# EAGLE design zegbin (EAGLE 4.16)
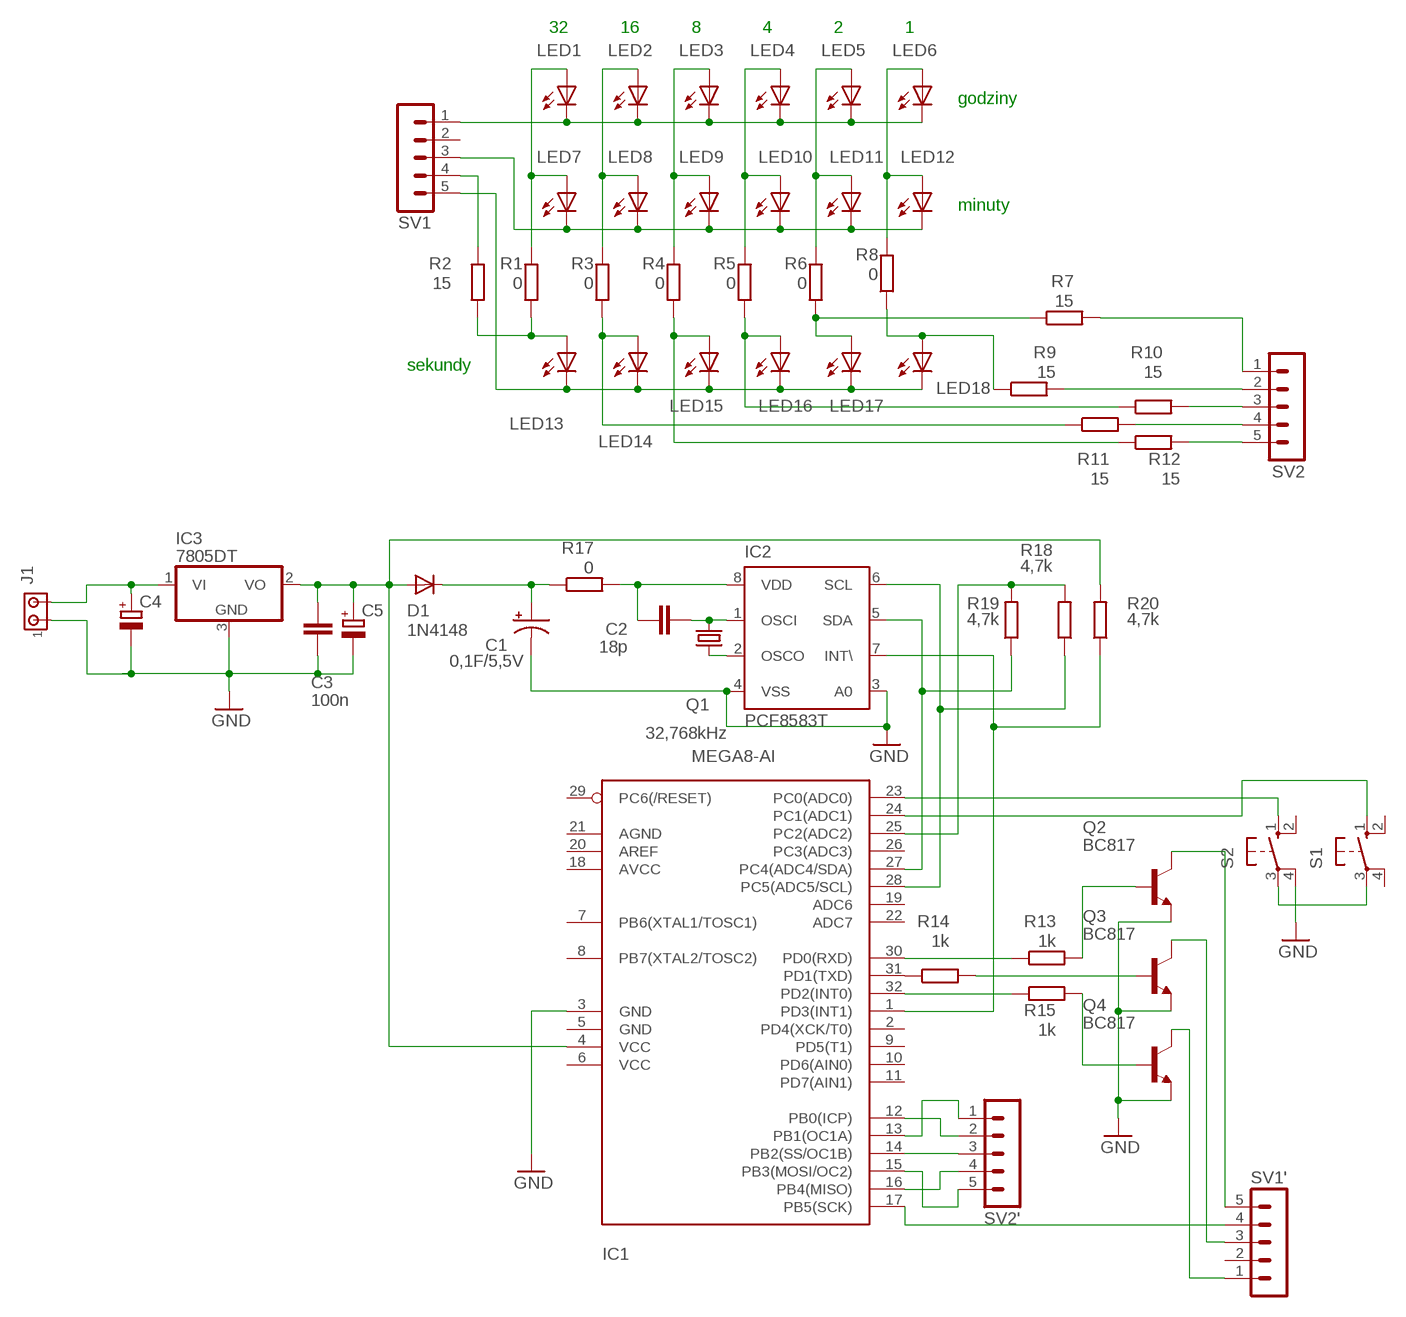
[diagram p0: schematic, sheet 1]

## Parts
C1  0,1F/5,5V  CPOL-USE5-13  [E5-13]
C2  18p  C-EUC1206  [C1206]
C3  100n  C-EUC1206  [C1206]
C4  CPOL-EU085CS-1AR  [085CS_1AR]
C5  CPOL-EU085CS-1AR  [085CS_1AR]
D1  1N4148  PMLL4150  [SOD80C]
IC1  MEGA8-AI  [TQFP32-08]
IC2  PCF8583T  [SO8-7_5]
IC3  7805DT  [TO252]
J1  MTA02-100  [10X02MTA]
LED1  LED5MM  [LED5MM]
LED2  LED5MM  [LED5MM]
LED3  LED5MM  [LED5MM]
LED4  LED5MM  [LED5MM]
LED5  LED5MM  [LED5MM]
LED6  LED5MM  [LED5MM]
LED7  LED5MM  [LED5MM]
LED8  LED5MM  [LED5MM]
LED9  LED5MM  [LED5MM]
LED10  LED5MM  [LED5MM]
LED11  LED5MM  [LED5MM]
LED12  LED5MM  [LED5MM]
LED13  LED5MM  [LED5MM]
LED14  LED5MM  [LED5MM]
LED15  LED5MM  [LED5MM]
LED16  LED5MM  [LED5MM]
LED17  LED5MM  [LED5MM]
LED18  LED5MM  [LED5MM]
Q1  32,768kHz  CRYSTALTC26H  [TC26H]
Q2  BC817  BC817-25SMD  [SOT23-BEC]
Q3  BC817  BC817-25SMD  [SOT23-BEC]
Q4  BC817  BC817-25SMD  [SOT23-BEC]
R1  0  R-EU_M1206  [M1206]
R2  15  R-EU_M1206  [M1206]
R3  0  R-EU_M1206  [M1206]
R4  0  R-EU_M1206  [M1206]
R5  0  R-EU_M1206  [M1206]
R6  0  R-EU_M1206  [M1206]
R7  15  R-EU_M1206  [M1206]
R8  0  R-EU_M1206  [M1206]
R9  15  R-EU_M1206  [M1206]
R10  15  R-EU_M1206  [M1206]
R11  15  R-EU_M1206  [M1206]
R12  15  R-EU_M1206  [M1206]
R13  1k  R-EU_M1206  [M1206]
R14  1k  R-EU_M1206  [M1206]
R15  1k  R-EU_M1206  [M1206]
R17  0  R-EU_M1206  [M1206]
R18  4,7k  R-EU_M1206  [M1206]
R19  4,7k  R-EU_M1206  [M1206]
R20  4,7k  R-EU_M1206  [M1206]
S1  10-XX  [B3F-10XX]
S2  10-XX  [B3F-10XX]
SV1  MA05-1  [MA05-1]
SV1'  MA05-1  [MA05-1]
SV2  MA05-1  [MA05-1]
SV2'  MA05-1  [MA05-1]

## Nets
GND: C1.- C3.1 C4.- C5.- IC1.3(GND) IC2.3(A0) IC2.4(VSS) IC3.3(GND) J1.1 Q2.E Q3.E Q4.E S2.4(P1)
N$1: LED1.K(C) LED2.K(C) LED3.K(C) LED4.K(C) LED5.K(C) LED6.K(C) SV1.1
N$2: LED7.K(C) LED8.K(C) LED9.K(C) LED10.K(C) LED11.K(C) LED12.K(C) SV1.3
N$3: LED13.K(C) LED14.K(C) LED15.K(C) LED16.K(C) LED17.K(C) LED18.K(C) SV1.5
N$4: LED1.A LED7.A R1.2
N$5: LED2.A LED8.A R3.2
N$6: LED3.A LED9.A R4.2
N$7: LED4.A LED10.A R5.2
N$8: LED5.A LED11.A R6.2
N$9: LED6.A LED12.A R8.2
N$10: LED13.A R1.1 R2.1
N$11: R2.2 SV1.4
N$12: LED14.A R3.1 R11.1
N$13: LED15.A R4.1 R12.1
N$14: LED16.A R5.1 R10.1
N$15: LED17.A R6.1 R7.1
N$16: R7.2 SV2.1
N$17: LED18.A R8.1 R9.1
N$18: R9.2 SV2.2
N$19: R10.2 SV2.3
N$20: R11.2 SV2.4
N$21: R12.2 SV2.5
N$22: C2.2 IC2.1(OSCI) Q1.2
N$23: IC2.2(OSCO) Q1.1
N$24: IC1.12(PB0(ICP)) SV2'.2
N$25: IC1.13(PB1(OC1A)) SV2'.1
N$26: IC1.14(PB2(SS/OC1B)) SV2'.3
N$27: IC1.16(PB4(MISO)) SV2'.4
N$28: IC1.15(PB3(MOSI/OC2)) SV2'.5
N$29: IC1.17(PB5(SCK)) SV1'.4
N$30: IC1.30(PD0(RXD)) R13.1
N$31: IC1.31(PD1(TXD)) R14.1
N$32: IC1.32(PD2(INT0)) R15.1
N$33: Q2.B R13.2
N$34: Q3.B R14.2
N$35: Q4.B R15.2
N$36: IC1.23(PC0(ADC0)) S2.1(S)
N$37: Q2.C SV1'.5
N$38: Q3.C SV1'.3
N$39: Q4.C SV1'.1
N$40: IC1.24(PC1(ADC1)) S1.1(S)
N$41: IC1.27(PC4(ADC4/SDA)) IC2.5(SDA) R19.1
N$43: IC1.28(PC5(ADC5/SCL)) IC2.6(SCL) R18.1
N$44: IC1.1(PD3(INT1)) IC2.7(INT\) R20.1
N$45: S1.3(P) S2.3(P)
N$46: C1.+ D1.C R17.1
N$48: C2.1 IC2.8(VDD) R17.2
N$49: C3.2 C5.+ D1.A IC1.4(VCC) IC3.2(VO) R20.2
N$50: C4.+ IC3.1(VI) J1.2
N$51: IC1.25(PC2(ADC2)) R18.2 R19.2
Unconnected: IC1.2(PD4(XCK/T0)) IC1.5(GND) IC1.6(VCC) IC1.7(PB6(XTAL1/TOSC1)) IC1.8(PB7(XTAL2/TOSC2)) IC1.9(PD5(T1)) IC1.10(PD6(AIN0)) IC1.11(PD7(AIN1)) IC1.18(AVCC) IC1.19(ADC6) IC1.20(AREF) IC1.21(AGND) IC1.22(ADC7) IC1.26(PC3(ADC3)) IC1.29(PC6(/RESET)) S1.2(S1) S1.4(P1) S2.2(S1) SV1'.2 SV1.2

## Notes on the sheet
- 32 | 16 | 8 | 4 | 2 | 1
- godziny
- minuty
- sekundy

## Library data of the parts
C1 = rcl:CPOL-US: POLARIZED CAPACITOR, American symbol
C2 C3 = rcl:C-EU: CAPACITOR, European symbol
C4 C5 = rcl:CPOL-EU: POLARIZED CAPACITOR, European symbol
D1 = diode:PMLL4150: DIODE
IC1 = avr-1:MEGA8: MICROCONTROLLER 8 Kbytes FLASH 1 kbytes SRAM 512 bytes EEPROM USART 6-channel 10 bit ADC 2-channel 8 bit ADC
IC2 = ds1307_pcf8583:PCF8583: I2C-Bus CLOCK/CALENDAR
IC3 = linear:78*: Positive VOLTAGE REGULATOR Source: http://cache.national.com/ds/LM/LM78L05.pdf http://www.fairchildsemi.com/ds/LM/LM7805.pdf
J1 = con-amp:MTA02-100: AMP connector
LED1-LED18 = led:LED: LED
Q1 = crystal:CRYSTAL: CRYSTAL
Q2-Q4 = transistor-npn:BC817*: NPN Transistor
R1-R15 R17-R20 = rcl:R-EU_: RESISTOR, European symbol
S1 S2 = switch-omron:10-XX: OMRON SWITCH
SV1 SV1' SV2 SV2' = con-lstb:MA05-1: PIN HEADER

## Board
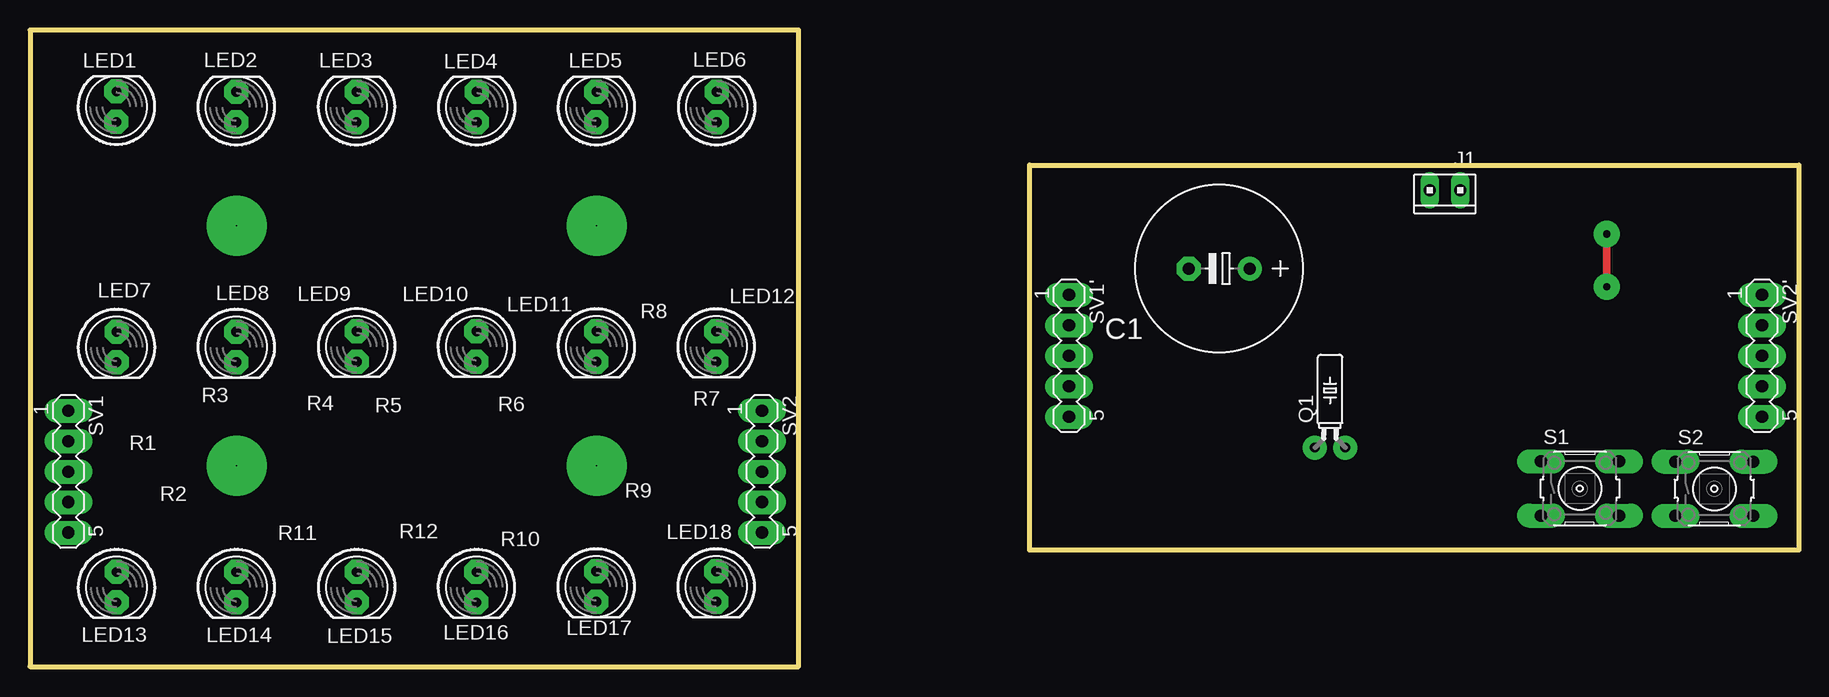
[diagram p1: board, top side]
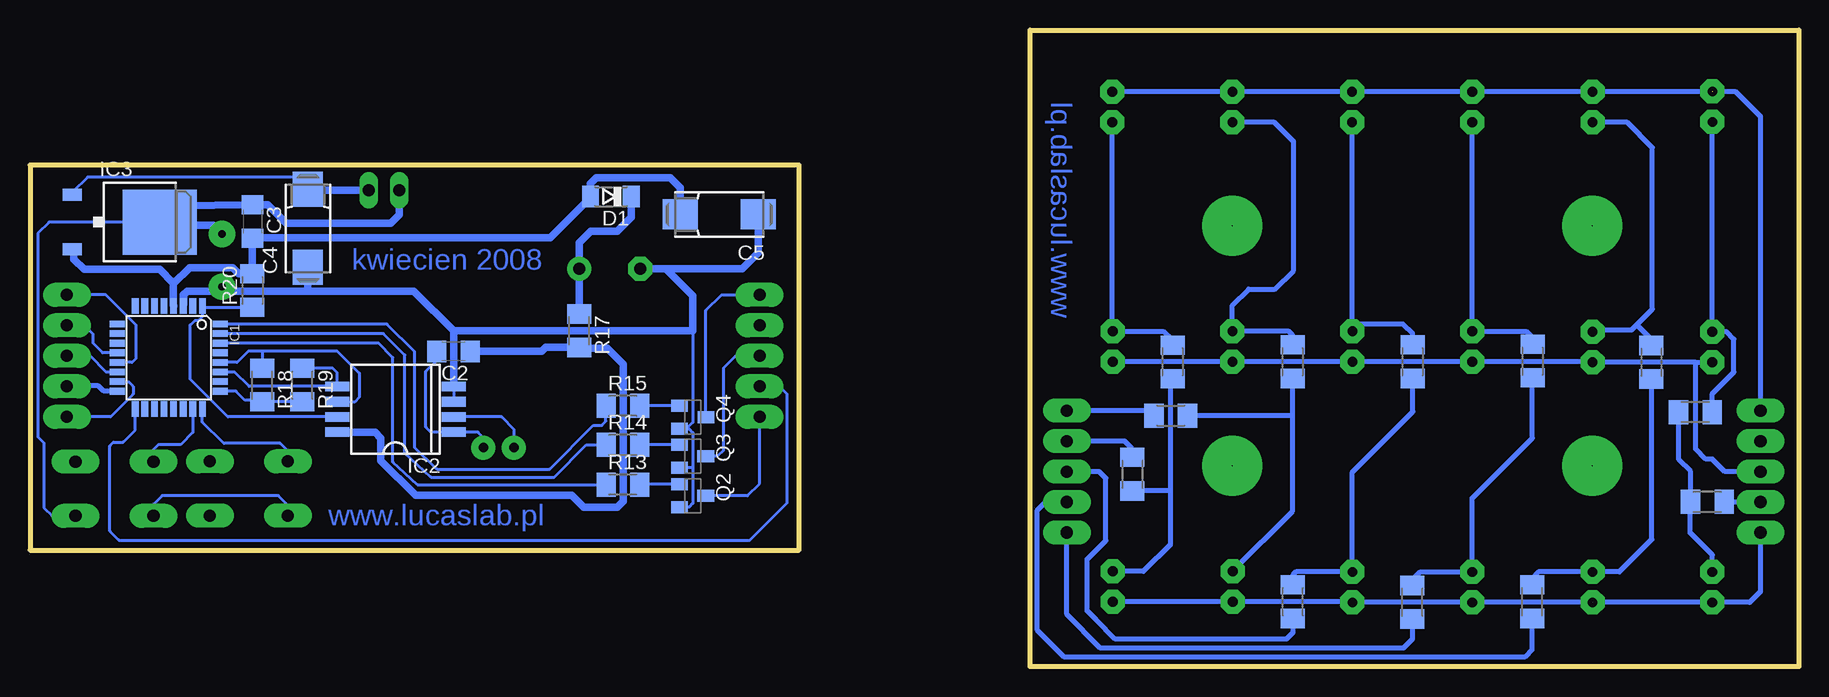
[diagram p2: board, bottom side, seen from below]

Size 147.4 x 53.05 mm. Coordinates in mm from the lower left corner, seen from the top.
Outline: 0,53.05 0,0 64.05,0 64.05,53.05 0,53.05
Outline: 83.3,41.8 147.4,41.8 147.4,9.7 83.3,9.7 83.3,41.8
Copper layers (1*16): Top 0.035mm / dielectric 1.5mm / Bottom 0.035mm
Design rules "default": minimum track width 10mil, minimum drill 24mil, track to track 8mil, track to pad 8mil, pad to pad 8mil, via to via 8mil, smd to smd 8mil, copper to edge 40mil, drill to drill 8mil, minimum pad ring 10mil, minimum via ring 8mil, stop-mask expansion 4mil, vias tented up to drill 0mil, thermal gap 10mil

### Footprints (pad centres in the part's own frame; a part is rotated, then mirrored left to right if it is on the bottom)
E5-13 = drill 1 pad 2 round: + -2.54,0 | drill 1 pad 2 octagon: - 2.54,0
C1206 = smd 1.6 x 1.8: 1 -1.4,0; 2 1.4,0
085CS_1AR = smd 2.9 x 2.5: + 3.25,0; - -3.25,0
SOD80C = smd 1.4 x 1.8: A 1.7,0; C -1.7,0
TQFP32-08 = smd 1.27 x 0.559: 1 -4.293,2.8; 2 -4.293,2; 3 -4.293,1.2; 4 -4.293,0.4; 5 -4.293,-0.4; 6 -4.293,-1.2; 7 -4.293,-2; 8 -4.293,-2.8; 17 4.293,-2.8; 18 4.293,-2; 19 4.293,-1.2; 20 4.293,-0.4; 21 4.293,0.4; 22 4.293,1.2; 23 4.293,2; 24 4.293,2.8 | smd 0.559 x 1.27: 9 -2.8,-4.293; 10 -2,-4.293; 11 -1.2,-4.293; 12 -0.4,-4.293; 13 0.4,-4.293; 14 1.2,-4.293; 15 2,-4.293; 16 2.8,-4.293; 25 2.8,4.293; 26 2,4.293; 27 1.2,4.293; 28 0.4,4.293; 29 -0.4,4.293; 30 -1.2,4.293; 31 -2,4.293; 32 -2.8,4.293
SO8-7_5 = smd 0.8 x 2: 1 -1.905,-4.845; 2 -0.635,-4.845; 3 0.635,-4.845; 4 1.905,-4.845; 5 1.905,4.845; 6 0.635,4.845; 7 -0.635,4.845; 8 -1.905,4.845
TO252 = smd 1 x 1.6: 1 -2.28,-4.8; 2 2.28,-4.8 | smd 5.4 x 6.2: 3 0,2.5
10X02MTA = drill 1.016 long: 1 1.27,0; 2 -1.27,0
LED5MM = drill 0.813 pad 2 octagon: A -1.27,0; K 1.27,0
TC26H = drill 0.813 pad 2 round: 1 -1.27,0; 2 1.27,0
SOT23-BEC = smd 1 x 1.4: B -0.95,-1.1; C 0,1.1; E 0.95,-1.1
M1206 = smd 1.6 x 2: 1 -1.4,0; 2 1.4,0
B3F-10XX = drill 1.016 pad 2 long: 1 -3.251,2.261; 2 3.251,2.261; 3 -3.251,-2.261; 4 3.251,-2.261
MA05-1 = drill 1.016 pad 2 long: 1 -5.08,0; 2 -2.54,0; 3 0,0; 4 2.54,0; 5 5.08,0

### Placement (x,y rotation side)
C1  99.1,33.17 180 top
C2  112.11,26.26 180 bottom
C3  128.86,37.09 270 bottom
C4  124.24,36.52 90 bottom
C5  89.96,37.68 180 bottom
D1  98.99,39.16 180 bottom
IC1  135.83,25.75 270 bottom
IC2  116.95,21.44 90 bottom
IC3  139.09,37.04 270 bottom
J1  117.91,39.7 180 top
LED1  7.2,46.66 90 top
LED2  17.19,46.62 90 top
LED3  27.21,46.62 90 top
LED4  37.23,46.62 90 top
LED5  47.2,46.62 90 top
LED6  57.22,46.62 90 top
LED7  7.21,26.62 270 top
LED8  17.19,26.62 270 top
LED9  27.22,26.68 270 top
LED10  37.2,26.68 270 top
LED11  47.2,26.67 270 top
LED12  57.18,26.67 270 top
LED13  7.21,6.62 270 top
LED14  17.19,6.62 270 top
LED15  27.22,6.62 270 top
LED16  37.2,6.62 270 top
LED17  47.18,6.67 270 top
LED18  57.18,6.67 270 top
Q1  108.34,18.25 0 top
Q2  92.18,14.23 270 bottom
Q3  92.18,17.53 270 bottom
Q4  92.17,20.78 270 bottom
R1  8.62,21.21 0 bottom
R2  7.62,13.72 0 bottom
R3  12.29,25.36 90 bottom
R4  22.19,25.46 90 bottom
R5  32.19,25.41 90 bottom
R6  42.19,25.41 90 bottom
R7  52.34,20.91 180 bottom
R8  52.19,25.39 90 bottom
R9  55.54,16.04 90 bottom
R10  42.16,5.41 270 bottom
R11  22.22,5.41 270 bottom
R12  32.21,5.36 270 bottom
R13  97.99,15.16 0 bottom
R14  97.99,18.47 0 bottom
R15  97.99,21.73 0 bottom
R17  101.64,27.99 270 bottom
R18  128.06,23.46 270 bottom
R19  124.7,23.46 270 bottom
R20  128.86,31.34 90 bottom
S1  129.16,14.84 0 top
S2  140.36,14.82 0 top
SV1  3.19,16.25 270 top
SV1'  86.59,25.9 270 top
SV2  61,16.25 270 top
SV2'  144.33,25.9 270 top

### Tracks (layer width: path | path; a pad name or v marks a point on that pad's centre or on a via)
GND  (via drill 0.6 pad 2.18)
  Top 0.61: v131.4,31.65 v131.4,36.05
  Bottom 0.254: 92.65,19.83 92.48,19.83 92.15,19.5 92.15,16.6 | 92.65,19.83 Q4.E | 92.15,16.6 92.15,13.6 92.45,13.3 93.25,13.3 Q2.E | Q3.E 92.17,16.58 92.15,16.6 | S2.4 145.56,12.56 146.25,13.25 146.25,17.65 146.27,18.68 146.75,19.15 146.75,36.1 145.8,37.05 139.15,37.05 137.14,35.04 136.59,35.04 | IC1.3 134.6,30 | 112.1,23.3 112.1,23.31 IC2.4 112.1,22.1 112.1,22.09 IC2.3 | 92.65,19.83 92.65,19.85 92.15,20.35 92.15,28 | 136.59,37.01 136.6,37 | 136.59,37.01 IC3.3 | 136.59,37.01 135.3,38.3 | 135.3,38.3 135.21,38.39 | 124.2,31.3 124.24,31.34 | 86.7,37.7 C5.- | 136.59,35.04 136.59,37.01 | 136.59,35.04 134.24,35.04 134.24,36.26 133.7,36.8 | IC3.3 136.55,37 | IC3.3 137.04,37.49 | 135.3,38.3 135.25,38.25 135.11,38.39
  Bottom 0.61: 134.3,31.3 134.63,30.97 134.63,30.12 134.65,30.1 | 131.4,31.3 124.2,31.3 115.4,31.3 112.1,28 | 112.1,28 112.1,23.3 | 94.42,33.17 C1.- | 94.42,33.17 92.15,30.9 92.15,28 112.1,28 | 124.24,31.34 C4.- | 94.42,33.17 88.03,33.17 86.7,34.5 86.7,37.7 | 135.11,38.39 C3.1 128.81,38.49 128.8,38.5 127.6,38.5 126.05,36.95 117.35,36.95 116.64,37.66 J1.1 | 134.63,30.08 IC1.3 | v131.39,36.04 v131.4,36.05 132.15,36.8 133.7,36.8 135.8,36.8 136,36.6 136.25,36.6 136.6,36.95 136.59,36.96 IC3.3 | 131.4,31.3 131.39,31.31 | 134.3,31.3 134.6,31 134.6,30.15 134.65,30.1 | 134.65,30.1 134.63,30.08 | 134.63,30.08 IC1.3 | 131.4,31.3 134.3,31.3 | 131.4,31.3 v131.4,31.65
N$1  (2 unrouted)
  Bottom 0.406: 47.3,47.89 LED5.K LED4.K | 47.3,47.89 LED6.K | 47.3,47.89 47.3,47.85 | LED4.K 37.15,47.89 37.15,47.9 | LED3.K 27,47.89 | LED3.K LED4.K | LED2.K 17.15,47.89 17.15,47.9 | LED2.K LED3.K | 7.2,47.89 LED2.K | SV1.1 3.19,45.84 5.25,47.9 7.2,47.9
N$2
  Bottom 0.406: LED11.K 47.15,25.4 | LED11.K LED12.K | LED11.K 37.15,25.4 37.16,25.4 LED10.K LED9.K | LED9.K 27.21,25.4 27.2,25.4 | LED9.K 17.21,25.4 17.19,25.39 LED8.K 8.6,25.35 | LED7.K | 8.6,25.35 LED7.K | SV1.3 6.15,16.25 7.2,17.3 7.75,17.3 8.6,18.15 8.6,25.35 | LED7.K | LED7.K
N$3  (1 unrouted)
  Bottom 0.406: LED17.K 47.1,5.4 | LED17.K LED18.K | LED17.K 37.2,5.4 LED16.K LED15.K 17.15,5.35 | LED14.K LED13.K 4.1,5.35 3.19,6.26 SV1.5
N$4
  Bottom 0.406: LED1.A 7.2,27.94 LED7.A 6,27.89 5.4,27.3 5.4,24.55 7.2,22.75 7.2,21.25 7.22,21.23 R1.2
N$5
  Bottom 0.406: LED2.A 14.31,45.35 12.2,43.25 12.2,29.8 13.5,28.5 | 13.5,28.5 13.95,28.05 17.05,28.05 LED8.A | R3.2 12.29,27.29 13.5,28.5
N$6
  Bottom 0.406: 27.21,27.91 27.22,27.92 LED9.A | 27.21,27.91 LED3.A | 27.21,27.91 27.2,27.9 22.65,27.9 22.2,27.45 22.2,26.95 22.19,26.94 R4.2
N$7
  Bottom 0.406: R5.2 32.19,27.74 33,28.55 36.6,28.55 LED10.A 37.2,45.35 37.21,45.35 LED4.A
N$8
  Bottom 0.406: LED5.A 43.71,45.35 42.1,43.75 42.1,33 43.65,31.45 45.85,31.45 47.2,30.1 LED11.A | LED11.A 47.2,27.9 | LED11.A 42.49,27.94 42.2,27.65 R6.2 42.19,26.79 | 42.19,26.79 42.15,26.75 | R6.2 42.19,26.79
N$9
  Bottom 0.406: 57.2,27.9 57.18,27.92 LED12.A | LED6.A 57.22,27.92 57.2,27.9 | R8.2 52.19,27.19 52.9,27.9 57.2,27.9
N$10
  Bottom 0.406: R1.1 10,21.2 10,17.25 9.02,16.27 R2.1 9.05,13.75 9.05,11.15 7.21,9.31 LED13.A
N$11
  Bottom 0.406: R2.2 6.17,13.72 6.15,13.7 6.14,13.71 SV1.4
N$12
  Bottom 0.406: R3.1 12.29,23.94 12.25,23.9 12.25,10.6 14.96,7.89 LED14.A 21.7,7.9 22.22,7.38 R11.1
N$13
  Bottom 0.406: R4.1 22.19,24.19 22.2,24.2 22.2,19.05 27.22,14.03 LED15.A 27.22,7.87 27.2,7.85 31.6,7.85 32.21,7.24 R12.1
N$14
  Bottom 0.406: LED16.A 37.2,16.2 32.15,21.25 32.15,24.05 R5.1 | R10.1 42.16,7.64 41.9,7.9 LED16.A | LED16.A
N$15
  Bottom 0.406: LED17.A 47.2,7.95 42.19,12.96 42.19,20.9 | 42.19,20.9 R6.1 | 42.19,20.9 42.2,20.9 42.21,20.91 R7.1
N$16
  Bottom 0.406: R7.2 53.74,20.94 54.13,21.33 SV2.1
N$17
  Bottom 0.406: LED18.A 54.61,7.94 52.35,10.2 52.35,14.65 | R8.1 52.35,23.85 52.35,14.65 | R9.1 52.36,14.64 52.35,14.65
N$18
  Bottom 0.406: SV2.2 56.19,18.79 55.55,18.15 55.55,17.4 55.54,17.41 R9.2
N$19
  Bottom 0.406: R10.2 42.16,2.84 42.7,2.3 56.95,2.3 58.55,3.9 | 58.55,3.9 58.85,4.2 | SV2.3 58.3,16.25 57.75,15.7 57.75,10.5 59.3,8.95 59.3,4.65 58.55,3.9
N$20
  Bottom 0.406: R11.2 22.22,1.43 22.85,0.8 61.2,0.8 63.45,3.05 63.45,13.05 62.8,13.7 60.95,13.7 60.96,13.71 SV2.4
N$21
  Bottom 0.406: R12.2 32.21,2.29 32.95,1.55 58.2,1.55 61,4.35 SV2.5 61,11.25
N$22
  Bottom 0.254: C2.2 113.51,25.49 114.4,24.6 114.4,19.95 114,19.55 IC2.1 110.09,19.53 109.6,19.05 109.61,19.04 Q1.2
N$23
  Bottom 0.254: IC2.2 108.1,20.81 107.05,19.75 107.05,18.25
  Bottom 0.406: Q1.1 107.05,18.25
N$24
  Bottom 0.254: IC1.12 141.35,26.15 142.15,26.95 142.15,27.7 142.9,28.45 144.35,28.45
  Bottom 0.406: 144.35,28.45 SV2'.2
N$25
  Bottom 0.254: IC1.13 138.9,25.35 138.55,25.7 138.55,28.45 141.1,31 144.3,31
  Bottom 0.406: 144.3,31 SV2'.1
N$26
  Bottom 0.254: IC1.14 141.05,24.55 142.4,25.9 SV2'.3
  Bottom 0.406: SV2'.3 144.35,25.9
N$27
  Bottom 0.406: IC1.16 141.25,22.95 141.7,23.4 144.25,23.4 144.3,23.35 144.31,23.36 SV2'.4
N$28
  Bottom 0.254: SV2'.5 140.68,20.82 138.8,22.7 138.8,23.35 139.15,23.7 140.05,23.7 140.1,23.75 IC1.15
N$29
  Bottom 0.254: SV1'.4 84.96,23.36 84.3,22.7 84.3,13.65 87.4,10.55 140,10.55 140.75,11.3 140.75,18.4 140.45,18.7 139.65,18.7 138.65,19.7 138.65,21.45 138.64,21.46 IC1.17
N$30
  Bottom 0.254: R13.1 115.11,15.16 117.15,17.05 117.15,25.75 118.35,26.95 131.65,26.95 | 131.65,26.95 IC1.30 | 131.65,26.95 131.7,27
N$31
  Bottom 0.254: R14.1 101.03,18.47 103.7,15.8 114,15.8 116.15,17.8 116.15,25.95 117.95,27.75 IC1.31
N$32
  Bottom 0.254: IC1.32 117.65,28.55 115.35,26.25 115.35,18.25 113.5,16.45 104.1,16.45 100.45,20.1 99.75,20.1 99.4,20.45 99.4,21.75 R15.1
N$33
  Bottom 0.254: 96.59,15.19 96.6,15.2 | 96.59,15.19 R13.2 | Q2.B 96.58,15.18 96.59,15.19
N$34
  Bottom 0.254: 96.59,18.49 96.6,18.5 | 96.59,18.49 R14.2 | Q3.B R14.2 96.59,18.49
N$35
  Bottom 0.254: 96.59,21.71 96.6,21.7 | 96.59,21.71 R15.2 | Q4.B 96.57,21.73 96.59,21.71
N$36
  Bottom 0.254: IC1.23 133.83,19.52 134.85,18.5 136.7,18.5 137.1,18.1 137.1,17.05 137.11,17.06 S2.1
N$37
  Bottom 0.254: Q2.C 87.62,14.23 86.6,15.25 86.6,20.85 86.59,20.84 SV1'.5
N$38
  Bottom 0.254: Q3.C 90.12,17.53 89.6,18.05 89.6,24.9 88.6,25.9 SV1'.3
N$39
  Bottom 0.254: SV1'.1 89.77,30.98 91.07,29.68 Q4.C
N$40
  Bottom 0.254: IC1.24 133.03,20.38 131.25,18.6 126.55,18.6 125.9,17.95 125.9,17.05 125.91,17.06 S1.1
N$41
  Bottom 0.254: IC1.27 131.54,24.56 131.5,24.6 131.45,24.55 130.35,24.55 129.14,23.34 IC2.5 121.8,23.31 121.8,23.3 121.8,24.5 122.16,24.86 R19.1
N$42
  Bottom 0.406: 86.6,30.95 86.6,31.05
N$43
  Bottom 0.254: IC2.6 121.77,22.07 121.75,22.05 120.35,22.05 119.95,22.45 119.95,24.45 121.8,26.3 128.05,26.3 | IC1.28 131.54,25.31 131.55,25.3 131.6,25.35 | 128.05,26.3 129.2,26.3 130.15,25.35 IC1.28 | IC1.28 | R18.1 128.06,26.29 128.05,26.3
N$44
  Bottom 0.254: IC2.7 130.9,20.81 134.05,23.95 134.05,28.45 133.65,28.85 133.35,28.85 133,29.2 133,30 IC1.1 | IC1.1 133.03,29.97 133.1,29.9 | IC1.1 133.03,30.02 133.05,30 132.99,29.94 R20.1
N$45
  Bottom 0.254: S1.3 125.91,13.46 126.7,14.25 136.4,14.25 137.1,13.55 S2.3 | S2.3
N$46
  Bottom 0.254: C1.+ 101.64,33.24 101.65,33.25 | 97.3,39.25 97.29,39.24 D1.C
  Bottom 0.61: R17.1 C1.+ 101.64,35.31 100.68,36.27 98.48,36.27 97.3,37.45 97.3,39.25
N$48
  Bottom 0.254: 101.7,26.55 101.66,26.59 R17.2
  Bottom 0.61: IC2.8 118.63,19.53 118.15,19.05 118.15,17.15 115.25,14.3 102.25,14.3 101.25,13.3 98.45,13.3 97.95,13.8 97.95,25.2 99.3,26.55 101.7,26.55 | C2.1 104.74,26.26 104.4,26.6 R17.2
N$49
  Bottom 0.254: 100.7,39.25 100.69,39.24 D1.A | IC3.2 143.81,34.76 143.75,34.7 143.76,34.69
  Bottom 0.61: C5.+ 93.21,39.91 94.05,40.75 100.2,40.75 100.7,40.25 100.7,39.25 | 135.45,31.9 134.1,33.25 130.5,33.25 129.99,32.74 R20.2 128.89,32.74 128.9,32.75 128.86,32.79 C3.2 128.86,35.74 104.06,35.74 103.25,36.55 | IC1.4 135.43,30.08 135.45,30.1 135.45,31.9 | 143.75,34.7 143.75,33.95 142.9,33.1 136.6,33.1 135.45,31.95 135.45,31.9 | D1.A 100.69,39.11 103.25,36.55 | 103.25,36.55 103.3,36.5
N$50
  Bottom 0.254: IC3.1 143.89,39.51 142.6,40.8 125.25,40.8 124.22,39.77 | 124.22,39.77 124.2,39.75 | C4.+ 124.22,39.77
  Bottom 0.61: C4.+ 124.24,39.71 124.25,39.7 J1.2
N$51
  Bottom 0.254: 128.34,22.19 128.35,22.2 | 128.34,22.19 R18.2 128.24,22.16 128.25,22.15 128.3,22.2 129.5,22.2 130.25,22.95 IC1.25 | R19.2 128.21,22.06 128.34,22.19
S$12  (via drill 0.1 pad 5)
  other vias: 47.22,16.73
S$26  (via drill 0.1 pad 5)
  other vias: 17.22,16.73
S$28  (via drill 0.1 pad 5)
  other vias: 47.22,36.73
S$29  (via drill 0.1 pad 5)
  other vias: 17.22,36.73

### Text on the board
Bottom: kwiecien 2008 | www.lucaslab.pl | www.lucaslab.pl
